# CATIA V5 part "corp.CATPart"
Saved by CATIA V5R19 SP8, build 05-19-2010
Part number: corp
Bounding box of the stored display mesh (mm): x -9.5 to 9.5, y -9.5 to 39.483, z -92.303 to 23.668
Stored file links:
  G:\EU_thinkMotion\CFAO_2010\MMS_groupe3\MMS_groupe3\A reprendre\ftixier\florent-tixier\florent-tixier\corp.CATPart
  C:\Users\Azote\Desktop\CFAO\coupe_tube1.CATProduct
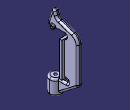
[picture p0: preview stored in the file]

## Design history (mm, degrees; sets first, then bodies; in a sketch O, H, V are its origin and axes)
Set1
  Point1: linked copy from another document
  Line1 "suport_axe_rouleau": linked copy from another document
  Line2 "Axe_vis": linked copy from another document
  Point2 "Centre_roulette_chanfreinage": linked copy from another document
Body1 (main body)
  Plane1: type OffsetPt, RefPlane xy-plane, RefPoint Point1
  Sketch1 on Plane1, origin (0, 0, -32.3031), H (1, 0, 0), V (0, 1, 0)
    line L1 (-4, 38.5) -> (-4, 18.5)
    line L2 (-4, 18.5) -> (-8.5, 18.5)
    line L3 (-8.5, 18.5) -> (-8.5, 14.5)
    line L4 (-8.5, 14.5) -> (8.5, 14.5)
    line L5 (8.5, 14.5) -> (8.5, 18.5)
    point P6 (8.5, 18.5)
    line L6 (8.5, 18.5) -> (4, 18.5)
    line L7 (4, 18.5) -> (4, 38.5)
    line L8 (4, 38.5) -> (-4, 38.5)
    reference projected line E1 (0, 20) -> (0, -20) from Line1
    reference projected line E2 (0, 20) -> (0, -20) from Line1
    length L8 = 8
    distance L7 E1 = 4
    length L4 = 17
    distance L3 E2 = 8.5
    length L3 = 4
    distance L4 H = 14.5
    length L7 = 20
    vertical: L1 V, L3 V, L5 V, L7 V
    horizontal: L2 H, L4 H, L6 H, L8 H
    coincidence: P6 L2
  Pad1: profile Sketch1, direction (0, 0, 1), length 25, opposite side length 30
  Sketch2 on face of Pad1 from Sketch1.L7, origin (4, 0, 0), H (0, 1, 0), V (0, 0, 1)
    line L1 (18.5, -62.3031) -> (21, -62.3031)
    arc A1 centre (21, -64.8031) radius 2.5 from (21, -62.3031) to (21, -67.3031) cw
    line L2 (21, -67.3031) -> (-1.5, -67.3031)
    line L3 (-1.5, -67.3031) -> (-1.5, -92.3031)
    line L4 (-1.5, -92.3031) -> (8.5, -92.3031)
    line L5 (8.5, -92.3031) -> (8.5, -89.3031)
    arc A2 centre (11.5, -89.3031) radius 3 from (8.5, -89.3031) to (9.6792, -86.9188) cw
    reference projected line E1 (0, -100) -> (0, 20) from Line2
    line L6 (9.6792, -86.9188) -> (38.0084, -65.284)
    arc A3 centre (35.7318, -62.3031) radius 3.7508 from (38.0084, -65.284) to (39.4826, -62.3031) ccw
    point P13 (39.4826, -62.3031)
    line L7 (39.4826, -62.3031) -> (39.4826, -7.3031)
    line L8 (18.5, -62.3031) -> (18.5, -7.3031)
    point P15 (18.5, -7.3031)
    point P16 (18.5, -7.3031)
    arc A4 centre (18.5, -3.6515) radius 3.6515 from (18.5, -7.3031) to (18.5, 0) ccw
    line L9 (18.5, 0) -> (3.5, 0)
    point P19 (3.5, 0)
    arc A5 centre (0, 0) radius 3.5 from (-3.5, 0) to (3.5, 0) ccw
    point P21 (-3.5, 0)
    reference projected point E2 (0, 0) from Point2
    line L10 (-3.5, 0) -> (-8.5, 0)
    line L11 (-8.5, 0) -> (-8.5, 4.9007)
    line L12 (-8.5, 4.9007) -> (-2.5, 22.5863)
    point P24 (-2.5, 22.5863)
    line L13 (-2.5, 22.5863) -> (2.5, 22.5863)
    line L14 (2.5, 22.5863) -> (4.7478, 16.6326)
    arc A6 centre (11.3949, 19.1422) radius 7.1051 from (4.7478, 16.6326) to (9.2765, 12.3602) ccw
    line L15 (9.2765, 12.3602) -> (30.7223, 5.1286)
    arc A7 centre (26.6077, -7.0733) radius 12.877 from (30.7223, 5.1286) to (39.4826, -7.3031) cw
    point P31 (-3.5, 0)
    point P32 (3.5, 0)
    reference projected line E3 (0, -100) -> (0, 20) from Line2
    length L3 = 25
    length L4 = 10
    distance L3 E1 = 1.5
    length L5 = 3
    radius A5 = 3.5
    length L10 = 5
    length L13 = 5
    distance E3 P24 = 2.5
    length L8 = 55
    horizontal: L1 H, L4 H, L13 H
    tangency: A1 L1, L2 A1, A2 L4, A2 L5, A3 L6, A3 L7, A2 L6, L9 A4, L10 A4, A6 L8, A6 L14, A7 L15, A1 L8
    vertical: L3 V, L5 V, L7 V, L8 V, L11 V
    coincidence: P13 L1, P16 P15, A5 P19, A5 P21, P21 L9, L9 H, L9 P32, L10 P31, P19 P32, P31 P21
    concentricity: A5 E2
  Pad2: profile Sketch2, direction (-1, 0, 0), length 8
  Sketch3 on face of Pad2 from Sketch2.L4, origin (0, 0, -92.3031), H (1, 0, 0), V (0, -1, 0)
    circle A1 centre (0, 0) radius 9.5
    radius A1 = 9.5
  Pad3: profile Sketch3, direction (0, 0, 1), length 25
  Sketch4 on face of Pad3, origin (5.8946, -0.6914, -67.3031), H (1, 0, 0), V (0, 1, 0)
    point P1 (-5.8946, 0.6914)
    reference projected point E1 (-5.8946, 0.6914) from Point2
    coincidence: P1 E1
  Hole1: placed by Sketch4, at (0, 0, -67.3031) direction (0, 0, -1), diameter 5, through (limit type 6), threaded, thread diameter 6, thread depth 10, pitch 1
  Sketch5 on zx-plane, origin (0, 0, 0), H (1, 0, 0), V (0, 0, 1)
    construction line L1 (0, 4.42) -> (0, -4.58)
    point P1 (0, 4.42)
    point P2 (0, -4.58)
    line L2 (2.6, 4.42) -> (2.6, 0)
    line L3 (-2.6, 0) -> (-2.6, 4.42)
    arc A1 centre (0, 4.42) radius 2.6 from (-2.6, 4.42) to (2.6, 4.42) cw
    point P4 (-2.6, -4.58)
    point P5 (-2.6, 4.42)
    line L4 (-2.6, 0) -> (2.6, 0)
    point P6 (-2.6, 0)
    distance L1 L2 = 2.6
    distance P2 H = 4.58
    distance P4 P5 = 9
    coincidence: P1 V, P6 H
    vertical: L1 V
    tangency: A1 L2, A1 L3
    horizontal: L4 H
  Line3: type Normal, RefPoint Point2, RefSkin face of Pad2, Start 0, End 20
  Groove1: profile Sketch5, axis Line3, angle 360
  Sketch6 on face of Pad2, origin (-4, -0.5493, 0.7764), H (0, 1, 0), V (0, 0, -1)
    point P1 (0.5493, 0.7764)
    reference projected point E1 (0.5493, 0.7764) from Point2
    coincidence: P1 E1
  Hole2: placed by Sketch6, at (-4, 0, 0) direction (1, 0, 0), diameter 4, through (limit type 3)
  Fillet1: radius 3, on edge [face of Pad2 | face of Pad2 from Sketch2.L15]; edge [face of Pad2 | face of Pad2 from Sketch2.A7]; edge [face of Pad2 | face of Pad2 from Sketch2.L7]; edge [face of Pad2 | face of Pad2 from Sketch2.A6]; edge [face of Pad2 | face of Pad2 from Sketch2.L14]; edge [face of Pad2 | face of Pad2 from Sketch2.L6]; edge [face of Pad2 | face of Pad2 from Sketch2.A3]
  Fillet2: radius 3, on edge [face of Pad2 from Sketch2.L14 | face of Pad2]; edge [face of Pad2 from Sketch2.A6 | face of Pad2]; edge [face of Pad2 from Sketch2.L15 | face of Pad2]; edge [face of Pad2 from Sketch2.A7 | face of Pad2]; edge [face of Pad2 from Sketch2.L7 | face of Pad2]; edge [face of Pad2 from Sketch2.A3 | face of Pad2]; edge [face of Pad2 from Sketch2.L6 | face of Pad2]; edge [face of Pad3 from Sketch3.A1 | face of Pad3]; edge [face of Pad3 | face of Pad3 from Sketch3.A1]; edge [face of Pad3 | face of Pad2]; edge [face of Pad2 | face of Pad3]; edge [face of Pad2 | face of Pad2 from Sketch2.A1]
  Fillet3: radius 3, on edge [face of Pad2 | face of Pad2 from Sketch2.L12]; edge [face of Pad2 from Sketch2.L12 | face of Pad2]; edge [face of Pad2 | face of Pad2 from Sketch2.L11]; edge [face of Pad2 from Sketch2.L11 | face of Pad2]; edge [face of Pad2 from Sketch2.L12 | face of Pad2 from Sketch2.L11]
  Sketch7 on face of Pad2, origin (-4, 0, 0), H (0, -1, 0), V (0, 0, 1)
    circle A1 centre (0, 0) radius 3.5
    circle A2 centre (0, 0) radius 2
    point P1 (0, 0)
    radius A1 = 3.5
    radius A2 = 2
    coincidence: P1 V
    concentricity: A2 A1
  Pad4: profile Sketch7, direction (-1, 0, 0), length 2
  Sketch8 on face of Pad2, origin (4, 0, 0), H (0, 1, 0), V (0, 0, 1)
    circle A1 centre (0, 0) radius 3.5
    circle A2 centre (0, 0) radius 2
    radius A1 = 3.5
    radius A2 = 2
  Pad5: profile Sketch8, direction (1, 0, 0), length 2
  Fillet4: radius 1, on edge [face of Pad2 | face of Pad4 from Sketch7.A1]
  Fillet5: radius 1, on edge [face of Pad4 from Sketch7.A1 | end face of Pad4]
  Fillet6: radius 1, on edge [face of Pad2 | face of Pad5 from Sketch8.A1]; edge [face of Pad5 from Sketch8.A1 | end face of Pad5]
  Fillet7: radius 1, on edge [face of Pad2 | face of Pad2 from Sketch2.A4]
  Fillet8: radius 1, on edge [face of Pad2 from Sketch2.L10 | face of Fillet3]
  Fillet9: radius 1, on edge [face of Pad2 from Sketch2.L9 | face of Pad2]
